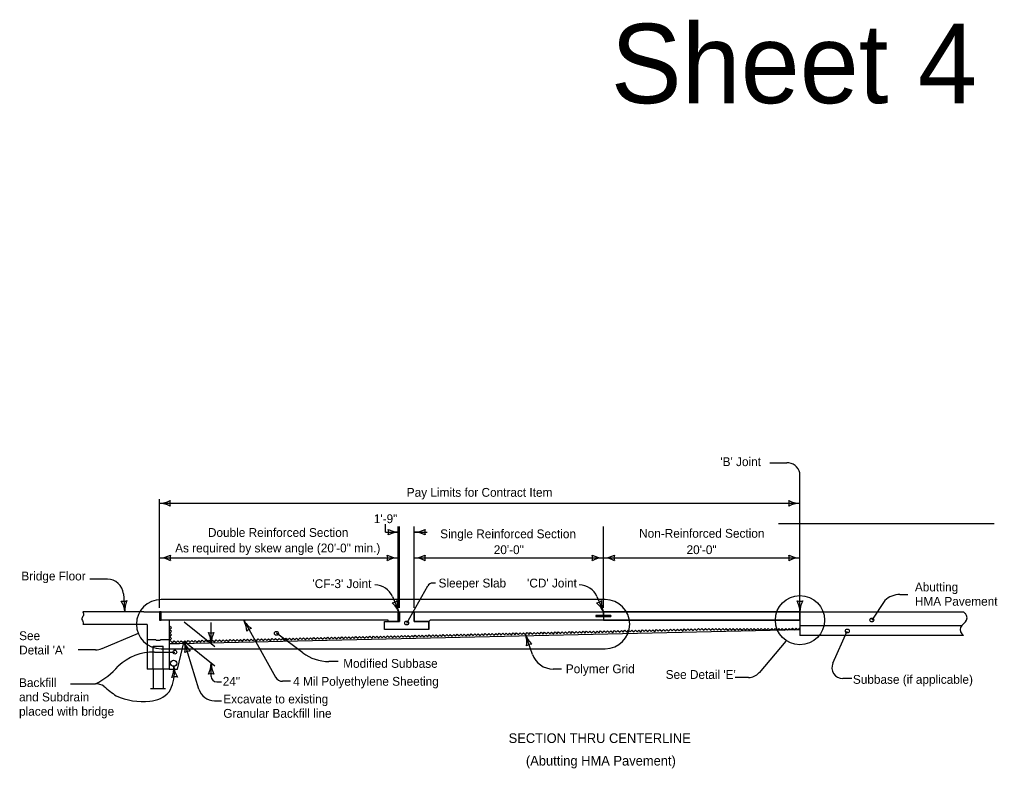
# Model space of a CAD drawing. Extents: x 10028 to 81668, y 6395 to 11634.
# Drawn here: x 21033 to 22806, y 6395 to 7754 of the extents above; entities that cross this region are included whole.
import ezdxf

# ---------------------------------------------------------------- set-up
doc = ezdxf.new("R2010")
doc.units = 0
for name, color, linetype in [('dsnCellElements', 7, 'Continuous'), ('dsnStdBlockNotModified', 7, 'Continuous'), ('dsnStdTextLabel', 7, 'Continuous'), ('dsnStgShadingPropPav', 7, 'Continuous'), ('ShtPlotIdentification', 7, 'Continuous')]:
    doc.layers.add(name, color=color, linetype=linetype)

msp = doc.modelspace()

# ---------------------------------------------------------------- linework, layer by layer
at = {"layer": 'dsnCellElements'}
for p, q in [((21696.4, 6824.1), (21696.4, 6838.8)), ((21696.4, 6824.1), (21721.6, 6824.1)), ((21748.3, 6824.1), (21772.3, 6824.1)), ((21734.9, 6659.2), (21773, 6726.6)), ((21787.2, 6731.7), (21781.7, 6731.7)), ((21289.5, 6664.6), (21289.5, 6679.4)), ((21289.5, 6679.4), (21719.7, 6679.4)), ((21289.5, 6664.6), (21289.5, 6679.4)), ((21719.7, 6679.4), (21719.7, 6675.6)), ((21719.7, 6675.6), (21719.7, 6670.8)), ((21719.7, 6670.8), (21719.7, 6662.2)), ((21721.6, 6672.9), (21721.6, 6671)), ((21748.3, 6676.8), (21748.3, 6679.4)), ((21748.3, 6679.4), (22091.4, 6679.4)), ((21748.3, 6674.5), (21748.3, 6676.8)), ((21748.3, 6672.9), (21748.3, 6674.5)), ((21748.3, 6671), (21748.3, 6672.9)), ((21748.3, 6662.2), (21748.3, 6672.9)), ((22078, 6672.9), (22078, 6671)), ((22091.4, 6672.9), (22078, 6672.9)), ((22078, 6672.9), (22078, 6671)), ((22078, 6671), (22091.4, 6671)), ((22091.4, 6672.9), (22091.4, 6679.4)), ((22091.4, 6679.4), (22091.4, 6672.9)), ((22104.7, 6672.9), (22091.4, 6672.9)), ((22091.4, 6671), (22091.4, 6664.5)), ((21304.7, 6664.6), (21289.5, 6664.6)), ((21326.6, 6664.5), (21304.7, 6664.6)), ((21701.5, 6664.5), (21326.6, 6664.5)), ((21439.5, 6664.5), (21496.8, 6561.2)), ((21701.5, 6662.2), (21701.5, 6664.5)), ((21719.7, 6662.2), (21701.5, 6662.2)), ((21775, 6662.2), (21748.3, 6662.2)), ((21777.5, 6664.5), (21775, 6662.2)), ((22091.4, 6664.5), (21777.5, 6664.5)), ((21277.7, 6606.5), (21314.5, 6606.5)), ((21125.2, 6549.1), (21170.9, 6549.1)), ((21524.1, 6553.5), (21509.9, 6553.5))]:
    msp.add_line(p, q, dxfattribs=at)
for centre, radius, start, end in [((21781.7, 6721.7), 10, 90, 150.5496), ((21275.5, 6515.7), 90.9, 88.6098, 134.2601), ((21107.4, 6674.4), 140.5, 296.876, 318.179), ((21242.5, 6569.5), 71.3, 330.5092, 2.0511), ((21509.9, 6568.5), 15, 209.0167, 270), ((21297.4, 6664.5), 163.6, 227.1442, 236.9942), ((21257.2, 6635.2), 118.5, 245.5915, 275.778), ((21264.5, 6572.1), 55, 274.8506, 316.7198)]:
    msp.add_arc(centre, radius, start, end, dxfattribs=at)
at = {"layer": 'dsnStdBlockNotModified'}
for centre, radius, start, end in [((21685.9, 6824.1), 16.4, 342.2666, 17.7333), ((21721.6, 6866.6), 42.5, 241.9275, 270), ((21748.3, 6866.6), 42.5, 270, 298.0725), ((21783.9, 6824.1), 16.4, 162.2666, 197.7334), ((21721.6, 6781.6), 42.5, 90, 118.0725), ((21748.3, 6781.6), 42.5, 61.9275, 90)]:
    msp.add_arc(centre, radius, start, end, dxfattribs=at)
at = {"layer": 'dsnStgShadingPropPav'}
for centre in [(22578.1, 6664.7), (21734.9, 6659.2), (22533.7, 6644.7), (21498.7, 6640.6), (21314.5, 6606.5)]:
    msp.add_circle(centre, 3.54, dxfattribs=at)
at = {"layer": 'ShtPlotIdentification'}
for p, q in [((22393.4, 6950), (22423.8, 6950)), ((22447.8, 6679.4), (22447.8, 6931.6)), ((21286.5, 6686.8), (21286.5, 6883.8)), ((21286.5, 6876.4), (22447.8, 6876.4)), ((21719.7, 6686.8), (21719.7, 6834.4)), ((21721.6, 6686.8), (21721.6, 6834.4)), ((21748.3, 6686.8), (21748.3, 6834.4)), ((22091.4, 6686.8), (22091.4, 6834.4)), ((22409.2, 6839.9), (22800.1, 6839.9)), ((21286.5, 6777.4), (21719.7, 6777.4)), ((21748.3, 6777.4), (22091.4, 6777.4)), ((22091.4, 6777.4), (22447.8, 6777.4)), ((21192.2, 6739), (21160.5, 6739)), ((21221.3, 6711.9), (21224.1, 6679.4)), ((22094.6, 6701.6), (21289.5, 6701.6)), ((21709.1, 6707.1), (21720.6, 6679.4)), ((22079.8, 6707.1), (22091.4, 6679.4)), ((22628.9, 6710.9), (22643.7, 6710.9)), ((22601.9, 6700.3), (22578.1, 6664.7)), ((21258.3, 6679.4), (21147.6, 6679.4)), ((21258.3, 6679.4), (21286.5, 6679.4)), ((21286.5, 6679.4), (21286.5, 6664.6)), ((21289.5, 6679.4), (21286.5, 6679.4)), ((21286.5, 6676), (21289.5, 6679)), ((21286.5, 6678.1), (21287.3, 6679)), ((21289.5, 6679), (21286.5, 6679)), ((21286.5, 6673.9), (21289.5, 6676.9)), ((21286.5, 6671.8), (21289.5, 6674.8)), ((21286.5, 6669.7), (21289.5, 6672.7)), ((21286.5, 6667.6), (21289.5, 6670.6)), ((21286.5, 6665.5), (21289.5, 6668.5)), ((21287.7, 6664.6), (21289.5, 6666.4)), ((21289.5, 6679.4), (21719.7, 6679.4)), ((21719.7, 6679.4), (21721.6, 6679.4)), ((21719.7, 6662.2), (21719.7, 6679.4)), ((21719.7, 6679.4), (21719.7, 6662.2)), ((21721.6, 6679.4), (21721.6, 6662.2)), ((21721.6, 6679.4), (21748.3, 6679.4)), ((21721.6, 6679.4), (21721.6, 6662.2)), ((21721.6, 6679.4), (21748.3, 6679.4)), ((21721.6, 6662.2), (21721.6, 6679.4)), ((21748.3, 6662.2), (21748.3, 6679.4)), ((21748.3, 6679.4), (22447.8, 6679.4)), ((21748.3, 6679.4), (21748.3, 6662.2)), ((21748.3, 6672.9), (21748.3, 6671)), ((22078, 6672.9), (22104.7, 6672.9)), ((22078, 6671), (22104.7, 6671)), ((22447.8, 6679.4), (22091.4, 6679.4)), ((22091.4, 6679.4), (22091.4, 6672.9)), ((22091.4, 6679.4), (22091.4, 6664.5)), ((22091.4, 6672.9), (22104.7, 6672.9)), ((22104.7, 6671), (22091.4, 6671)), ((22091.4, 6671), (22091.4, 6664.5)), ((22104.7, 6672.9), (22104.7, 6671)), ((22104.7, 6672.9), (22104.7, 6671)), ((22447.8, 6664.5), (22447.8, 6679.4)), ((22447.8, 6679.4), (22744.6, 6679.4)), ((22447.8, 6679.4), (22447.8, 6664.5)), ((22729.9, 6679.4), (22729.9, 6679.4)), ((22747.7, 6676.2), (22744.6, 6679.4)), ((21264.2, 6656.5), (21147.6, 6656.5)), ((21264.2, 6656.5), (21264.2, 6575.6)), ((21286.5, 6664.6), (21289.5, 6664.6)), ((21701.5, 6664.5), (21289.5, 6664.5)), ((21304.3, 6664.6), (21304.3, 6575.6)), ((21331.6, 6661.6), (21386.9, 6616.6)), ((21380.4, 6621.8), (21380.4, 6660)), ((21694.9, 6647.3), (21694.9, 6662.2)), ((21694.9, 6662.2), (21701.5, 6662.2)), ((21694.9, 6647.3), (21694.9, 6662.2)), ((21694.9, 6662.2), (21701.5, 6662.2)), ((21701.5, 6662.2), (21701.5, 6664.5)), ((21701.5, 6662.2), (21721.6, 6662.2)), ((21701.5, 6662.2), (21721.6, 6662.2)), ((21721.6, 6662.2), (21719.7, 6662.2)), ((21775, 6662.2), (21748.3, 6662.2)), ((21748.3, 6662.2), (21775, 6662.2)), ((21775, 6662.2), (21777.5, 6664.5)), ((21775, 6647.3), (21775, 6662.2)), ((21775, 6662.2), (21775, 6647.3)), ((22447.8, 6664.5), (21777.5, 6664.5)), ((22091.4, 6664.5), (22447.8, 6664.5)), ((22447.8, 6664.5), (22447.8, 6636.8)), ((22447.8, 6654.6), (22741.2, 6654.6)), ((22741.4, 6654.9), (22747.7, 6661.1)), ((21248.3, 6640.1), (21182.1, 6612.7)), ((22447.8, 6646.9), (21323.1, 6621.5)), ((21546.7, 6605), (21498.7, 6640.6)), ((21775, 6647.3), (21694.9, 6647.3)), ((21775, 6647.3), (21694.9, 6647.3)), ((21962.9, 6602.4), (21950.4, 6638.4)), ((22744.4, 6636.8), (22447.8, 6636.8)), ((22507.4, 6586.4), (22533.7, 6644.7)), ((22744.6, 6636.6), (22741.4, 6639.7)), ((21264.2, 6629.3), (21279.3, 6629.3)), ((21275, 6575.6), (21275, 6617.3)), ((21275, 6617.3), (21293.5, 6617.3)), ((21281.2, 6627.6), (21279.3, 6629.3)), ((21287.3, 6627.6), (21281.2, 6627.6)), ((21287.3, 6627.6), (21289.2, 6629.3)), ((21289.2, 6629.3), (21304.3, 6629.3)), ((21293.5, 6575.6), (21293.5, 6617.3)), ((21323.1, 6621.5), (21304.3, 6621.5)), ((21319.2, 6575.6), (21331.6, 6626.3)), ((21331.6, 6626.3), (21386.9, 6581.3)), ((21358.1, 6539.4), (21331.6, 6626.3)), ((22422.2, 6626.3), (22373.7, 6569.2)), ((21170.8, 6610.5), (21139.2, 6610.5)), ((21289.5, 6612.5), (22094.6, 6612.5)), ((21380.4, 6562.5), (21380.4, 6586.5)), ((21610.8, 6589.4), (21593.9, 6589.4)), ((21304.3, 6575.6), (21264.2, 6575.6)), ((21275, 6575.6), (21275, 6540.7)), ((21293.5, 6575.6), (21293.5, 6540.7)), ((21304.3, 6575.6), (21319.2, 6575.6)), ((22015.6, 6575.8), (22000.3, 6575.8)), ((22354.6, 6560.5), (22330.4, 6560.5)), ((21390.4, 6552.5), (21399, 6552.5)), ((22541.7, 6558.5), (22525.5, 6558.5)), ((21270.7, 6540.7), (21297.7, 6540.7)), ((21386.5, 6518.4), (21399, 6518.4))]:
    msp.add_line(p, q, dxfattribs=at)
for points in [[(21307.3, 6626.4), (21305.5, 6628.1), (21308.6, 6631.3), (21305.4, 6634.4), (21308.5, 6637.6), (21305.2, 6640.7), (21308.3, 6644), (21305.1, 6647.1), (21308.2, 6650.3), (21304.9, 6653.4), (21305.1, 6653.5)], [(22201.9, 6646), (22203.5, 6644.5), (22206.6, 6647.7), (22209.8, 6644.6), (22212.9, 6647.9), (22216.2, 6644.8), (22219.2, 6648), (22222.5, 6644.9), (22225.6, 6648.2), (22228.8, 6645.1), (22231.9, 6648.3), (22235.2, 6645.2), (22238.2, 6648.5), (22241.5, 6645.4), (22244.6, 6648.6), (22247.8, 6645.5), (22250.9, 6648.8), (22254.2, 6645.7), (22257.3, 6648.9), (22260.5, 6645.8), (22263.6, 6649.1), (22266.8, 6646), (22269.9, 6649.2), (22273.2, 6646.1), (22276.3, 6649.4), (22277.9, 6647.8)], [(22277.9, 6648), (22279.5, 6646.4), (22282.6, 6649.6), (22285.8, 6646.4), (22289, 6649.6), (22292.1, 6646.4), (22295.3, 6649.6), (22298.5, 6646.4), (22301.6, 6649.6), (22304.8, 6646.4), (22308, 6649.6), (22311.1, 6646.4), (22314.3, 6649.6), (22317.5, 6646.4), (22320.6, 6649.6), (22323.8, 6646.4), (22327, 6649.6), (22330.1, 6646.4), (22333.3, 6649.6), (22336.5, 6646.5), (22339.6, 6649.6), (22342.8, 6646.5), (22346, 6649.6), (22349.1, 6646.5), (22352.3, 6649.6), (22353.9, 6648.1)], [(22353.9, 6647.8), (22355.5, 6646.3), (22358.6, 6649.4), (22361.8, 6646.3), (22365, 6649.4), (22368.2, 6646.3), (22371.3, 6649.4), (22374.5, 6646.3), (22377.7, 6649.4), (22380.8, 6646.3), (22384, 6649.5), (22387.2, 6646.3), (22390.3, 6649.5), (22393.5, 6646.3), (22396.7, 6649.5), (22399.8, 6646.3), (22403, 6649.5), (22406.2, 6646.3), (22409.3, 6649.5), (22412.5, 6646.3), (22415.7, 6649.5), (22418.8, 6646.3), (22422, 6649.5), (22425.2, 6646.3), (22428.3, 6649.5), (22429.9, 6647.9)], [(22429.9, 6648.3), (22431.5, 6646.7), (22434.6, 6649.9), (22437.8, 6646.7), (22441, 6649.9), (22444.2, 6646.7), (22447.3, 6649.9), (22447.8, 6649.4)], [(21441.8, 6628.2), (21443.4, 6626.7), (21446.5, 6629.9), (21449.7, 6626.8), (21452.8, 6630.1), (21456, 6627), (21459.1, 6630.2), (21462.4, 6627.1), (21465.5, 6630.4), (21468.7, 6627.3), (21471.8, 6630.5), (21475, 6627.4), (21478.1, 6630.7), (21481.4, 6627.6), (21484.5, 6630.8), (21487.7, 6627.7), (21490.8, 6631), (21494, 6627.9), (21497.1, 6631.1), (21500.4, 6628), (21503.5, 6631.3), (21506.7, 6628.2), (21509.8, 6631.4), (21513.1, 6628.3), (21516.1, 6631.6), (21517.8, 6630)], [(21517.8, 6630), (21519.4, 6628.5), (21522.5, 6631.7), (21525.7, 6628.6), (21528.8, 6631.9), (21532.1, 6628.8), (21535.1, 6632), (21538.4, 6628.9), (21541.5, 6632.2), (21544.7, 6629.1), (21547.8, 6632.3), (21551.1, 6629.2), (21554.2, 6632.5), (21557.4, 6629.4), (21560.5, 6632.6), (21563.7, 6629.5), (21566.8, 6632.8), (21570.1, 6629.7), (21573.2, 6632.9), (21576.4, 6629.8), (21579.5, 6633.1), (21582.7, 6630), (21585.8, 6633.2), (21589.1, 6630.1), (21592.2, 6633.4), (21593.8, 6631.8)], [(21593.8, 6631.8), (21595.4, 6630.3), (21598.5, 6633.5), (21601.7, 6630.4), (21604.8, 6633.7), (21608.1, 6630.6), (21611.2, 6633.8), (21614.4, 6630.7), (21617.5, 6634), (21620.7, 6630.9), (21623.8, 6634.1), (21627.1, 6631), (21630.2, 6634.3), (21633.4, 6631.2), (21636.5, 6634.4), (21639.7, 6631.3), (21642.8, 6634.6), (21646.1, 6631.5), (21649.2, 6634.7), (21652.4, 6631.6), (21655.5, 6634.8), (21658.7, 6631.8), (21661.8, 6635), (21665.1, 6631.9), (21668.2, 6635.1), (21669.8, 6633.6)], [(21669.8, 6633.6), (21671.4, 6632), (21674.5, 6635.3), (21677.7, 6632.2), (21680.8, 6635.4), (21684.1, 6632.3), (21687.2, 6635.6), (21690.4, 6632.5), (21693.5, 6635.7), (21696.7, 6632.6), (21699.8, 6635.9), (21703.1, 6632.8), (21706.2, 6636), (21709.4, 6632.9), (21712.5, 6636.2), (21715.8, 6633.1), (21718.8, 6636.3), (21722.1, 6633.2), (21725.2, 6636.5), (21728.4, 6633.4), (21731.5, 6636.6), (21734.8, 6633.5), (21737.8, 6636.8), (21741.1, 6633.7), (21744.2, 6636.9), (21745.8, 6635.4)], [(21745.8, 6635.4), (21747.4, 6633.8), (21750.5, 6637.1), (21753.8, 6634), (21756.8, 6637.2), (21760.1, 6634.1), (21763.2, 6637.4), (21766.4, 6634.3), (21769.5, 6637.5), (21772.8, 6634.4), (21775.8, 6637.7), (21779.1, 6634.6), (21782.2, 6637.8), (21785.4, 6634.7), (21788.5, 6638), (21791.8, 6634.9), (21794.9, 6638.1), (21798.1, 6635), (21801.2, 6638.3), (21804.4, 6635.2), (21807.5, 6638.4), (21810.8, 6635.3), (21813.9, 6638.6), (21817.1, 6635.5), (21820.2, 6638.7), (21821.8, 6637.2)], [(21821.8, 6637.2), (21823.4, 6635.6), (21826.5, 6638.9), (21829.8, 6635.8), (21832.9, 6639), (21836.1, 6635.9), (21839.2, 6639.2), (21842.4, 6636.1), (21845.5, 6639.3), (21848.8, 6636.2), (21851.9, 6639.5), (21855.1, 6636.4), (21858.2, 6639.6), (21861.4, 6636.5), (21864.5, 6639.8), (21867.8, 6636.7), (21870.9, 6639.9), (21874.1, 6636.8), (21877.2, 6640.1), (21880.4, 6637), (21883.5, 6640.2), (21886.8, 6637.1), (21889.9, 6640.4), (21893.1, 6637.3), (21896.2, 6640.5), (21897.8, 6639)], [(21897.8, 6638.9), (21899.4, 6637.4), (21902.5, 6640.6), (21905.8, 6637.5), (21908.9, 6640.8), (21912.1, 6637.7), (21915.2, 6640.9), (21918.4, 6637.8), (21921.5, 6641.1), (21924.8, 6638), (21927.9, 6641.2), (21931.1, 6638.1), (21934.2, 6641.4), (21937.4, 6638.3), (21940.5, 6641.5), (21943.8, 6638.4), (21946.9, 6641.7), (21950.1, 6638.6), (21953.2, 6641.8), (21956.4, 6638.7), (21959.5, 6642), (21962.8, 6638.9), (21965.9, 6642.1), (21969.1, 6639), (21972.2, 6642.3), (21973.8, 6640.7)], [(21973.8, 6640.7), (21975.5, 6639.2), (21978.5, 6642.4), (21981.8, 6639.3), (21984.9, 6642.5), (21988.1, 6639.4), (21991.2, 6642.7), (21994.5, 6639.6), (21997.5, 6642.8), (22000.8, 6639.7), (22003.9, 6643), (22007.1, 6639.9), (22010.2, 6643.1), (22013.5, 6640), (22016.6, 6643.3), (22019.8, 6640.2), (22022.9, 6643.4), (22026.1, 6640.3), (22029.2, 6643.6), (22032.5, 6640.5), (22035.6, 6643.7), (22038.8, 6640.6), (22041.9, 6643.9), (22045.1, 6640.8), (22048.2, 6644), (22049.8, 6642.5)], [(22049.8, 6642.5), (22051.5, 6640.9), (22054.6, 6644.2), (22057.8, 6641.1), (22060.9, 6644.3), (22064.1, 6641.2), (22067.2, 6644.5), (22070.5, 6641.4), (22073.6, 6644.6), (22076.8, 6641.5), (22079.9, 6644.7), (22083.1, 6641.7), (22086.2, 6644.9), (22089.5, 6641.8), (22092.6, 6645), (22095.8, 6642), (22098.9, 6645.2), (22102.1, 6642.1), (22105.2, 6645.3), (22108.5, 6642.3), (22111.6, 6645.5), (22114.8, 6642.4), (22117.9, 6645.6), (22121.1, 6642.5), (22124.2, 6645.8), (22125.9, 6644.2)], [(22125.9, 6644.3), (22127.5, 6642.7), (22130.6, 6646), (22133.8, 6642.9), (22136.9, 6646.1), (22140.1, 6643), (22143.2, 6646.3), (22146.5, 6643.2), (22149.6, 6646.4), (22152.8, 6643.3), (22155.9, 6646.5), (22159.1, 6643.5), (22162.2, 6646.7), (22165.5, 6643.6), (22168.6, 6646.8), (22171.8, 6643.7), (22174.9, 6647), (22178.2, 6643.9), (22181.2, 6647.1), (22184.5, 6644), (22187.6, 6647.3), (22190.8, 6644.2), (22193.9, 6647.4), (22197.2, 6644.3), (22200.2, 6647.6), (22201.9, 6646)], [(21307, 6626.5), (21307.1, 6626.6), (21310.4, 6623.5), (21313.4, 6626.7), (21316.7, 6623.7), (21319.8, 6626.9), (21323, 6623.8), (21326.1, 6627), (21329.4, 6624), (21332.5, 6627.2), (21335.7, 6624.1), (21338.8, 6627.3), (21342, 6624.2), (21345.1, 6627.5), (21348.4, 6624.4), (21351.5, 6627.6), (21354.7, 6624.5), (21357.8, 6627.8), (21361, 6624.7), (21364.1, 6627.9), (21365.7, 6626.4)], [(21365.7, 6626.5), (21367.4, 6624.9), (21370.5, 6628.2), (21373.7, 6625.1), (21376.8, 6628.3), (21380, 6625.2), (21383.1, 6628.4), (21386.4, 6625.4), (21389.5, 6628.6), (21392.7, 6625.5), (21395.8, 6628.7), (21399, 6625.7), (21402.1, 6628.9), (21405.4, 6625.8), (21408.5, 6629), (21411.7, 6626), (21414.8, 6629.2), (21418, 6626.1), (21421.1, 6629.3), (21424.4, 6626.2), (21427.5, 6629.5), (21430.7, 6626.4), (21433.8, 6629.6), (21437, 6626.5), (21440.1, 6629.8), (21441.8, 6628.2)]]:
    msp.add_lwpolyline(points, dxfattribs=at)
for centre, radius in [((22447.8, 6664.5), 44.6), ((21312.3, 6586.3), 5.57)]:
    msp.add_circle(centre, radius, dxfattribs=at)
for centre, radius, start, end in [((22423.8, 6925.2), 24.8, 15.0299, 90), ((21285.9, 6919.1), 42.7, 270, 298.0725), ((21321.7, 6876.4), 16.5, 162.2666, 197.7334), ((22411.9, 6876.4), 16.5, 342.2666, 17.7333), ((22447.8, 6919.1), 42.7, 241.9275, 270), ((21285.9, 6833.6), 42.7, 61.9275, 90), ((22447.8, 6833.6), 42.7, 90, 118.0725), ((21286.5, 6820.1), 42.7, 270, 298.0725), ((21286.5, 6734.6), 42.7, 61.9275, 90), ((21322.3, 6777.4), 16.5, 162.2666, 197.7334), ((21683.9, 6777.4), 16.5, 342.2666, 17.7333), ((21719.7, 6820.1), 42.7, 241.9275, 270), ((21719.7, 6734.6), 42.7, 90, 118.0725), ((21748.3, 6820.1), 42.7, 270, 298.0725), ((21748.3, 6734.6), 42.7, 61.9275, 90), ((21784.2, 6777.4), 16.5, 162.2666, 197.7334), ((22055.5, 6777.4), 16.5, 342.2666, 17.7333), ((22091.4, 6820.1), 42.7, 241.9275, 270), ((22091.4, 6734.6), 42.7, 90, 118.0725), ((22091.4, 6820.1), 42.7, 270, 298.0725), ((22091.4, 6734.6), 42.7, 61.9275, 90), ((22127.2, 6777.4), 16.5, 162.2666, 197.7334), ((22411.9, 6777.4), 16.5, 342.2666, 17.7333), ((22447.8, 6820.1), 42.7, 241.9275, 270), ((22447.8, 6734.6), 42.7, 90, 118.0725), ((21191.7, 6709.3), 29.7, 4.9696, 89.1065), ((21677.1, 6693.8), 34.7, 22.5907, 90), ((22047.8, 6693.8), 34.7, 22.5907, 90), ((21289.5, 6657.1), 44.6, 90, 269.9998), ((22094.6, 6657.1), 44.6, 270.0002, 90), ((22628.9, 6671.3), 39.6, 90, 132.998), ((21221, 6715.1), 16.5, 257.2356, 292.7023), ((21181.5, 6675.7), 42.7, 4.969, 33.0415), ((21266.7, 6683.1), 42.7, 156.8965, 184.969), ((21706.9, 6712.5), 16.5, 274.8595, 310.3262), ((21681.2, 6662.9), 42.7, 22.5928, 50.6653), ((21760.1, 6695.8), 42.7, 174.5203, 202.5928), ((22077.6, 6712.5), 16.5, 274.8572, 310.3239), ((22051.9, 6662.9), 42.7, 22.5905, 50.663), ((22130.8, 6695.8), 42.7, 174.5181, 202.5905), ((22447.8, 6715.2), 16.5, 252.2666, 287.7333), ((22405, 6679.4), 42.7, 360, 28.0725), ((22490.5, 6679.4), 42.7, 151.9275, 180), ((22740.1, 6668.7), 10.7, 315, 45), ((21476.8, 6685.3), 42.7, 209.0167, 237.0892), ((21402.1, 6643.8), 42.7, 0.9442, 29.0167), ((21456.8, 6633.2), 16.5, 101.2834, 136.7501), ((22749, 6647.3), 10.7, 135, 225), ((21380.4, 6657.7), 16.5, 252.2666, 287.7333), ((21337.7, 6621.8), 42.7, 360, 28.0725), ((21423.1, 6621.8), 42.7, 151.9275, 180), ((21990.8, 6652.4), 42.7, 199.1779, 227.2504), ((21910, 6624.3), 42.7, 351.1054, 19.1779), ((21170.7, 6640.2), 29.7, 270, 292.4496), ((21372.5, 6638.7), 42.7, 196.9537, 225.0262), ((21290.7, 6613.8), 42.7, 348.8812, 16.9537), ((21962.2, 6604.5), 16.5, 91.4446, 126.9113), ((21342, 6592), 16.5, 89.2203, 124.687), ((21593.9, 6668.6), 79.2, 233.4243, 270), ((22000.3, 6615.4), 39.6, 199.1769, 270), ((21270.2, 6576.9), 42.5, 337.1139, 5.1864), ((21354.8, 6584.6), 42.5, 185.1864, 213.2589), ((21337.7, 6586.5), 42.7, 331.9275, 360), ((21423.1, 6586.5), 42.7, 180, 208.0725), ((22525.5, 6578.3), 19.8, 155.762, 270), ((21315.7, 6545.2), 16.4, 77.453, 112.9197), ((21380.4, 6550.7), 16.5, 72.2666, 107.7334), ((21390.4, 6562.5), 10, 180, 270), ((22354.6, 6585.5), 25, 270, 319.6052), ((21170.9, 6521.4), 27.7, 56.8248, 90), ((21386.5, 6548.1), 29.7, 196.9535, 270)]:
    msp.add_arc(centre, radius, start, end, dxfattribs=at)
msp.add_spline([(21147.6, 6679.4), (21148.8, 6673.4), (21145.8, 6667.4), (21148.6, 6659.8), (21148.2, 6656.5)], degree=3, dxfattribs=at)

# ---------------------------------------------------------------- texts
at = {"layer": 'dsnCellElements'}
for s, height, p in [("'B' Joint", 16, (22303.6, 6943.8)), ('Pay Limits for Contract Item', 16, (21735, 6888.2)), ('1\'-9"', 16, (21675.3, 6840.4)), ('Double Reinforced Section', 16, (21374.6, 6815.4)), ('Single Reinforced Section', 16, (21795.6, 6813)), ('Non-Reinforced Section', 16, (22156.3, 6813.9)), ('As required by skew angle (20\'-0" min.)', 16, (21315.1, 6787.3)), ('20\'-0"', 16, (21892.7, 6784.2)), ('20\'-0"', 16, (22242.2, 6784.2)), ('Bridge Floor', 16, (21036.3, 6736.5)), ("'CF-3' Joint", 16, (21564.1, 6722.6)), ('Sleeper Slab', 16, (21792.6, 6723.7)), ("'CD' Joint", 16, (21953.2, 6723.7)), ('Abutting', 16, (22656.2, 6716.6)), ('HMA Pavement', 16, (22656.2, 6690.6)), ('See', 16, (21032.3, 6628.2)), ("Detail 'A'", 16, (21032.3, 6602.2)), ('Modified Subbase', 16, (21619.8, 6578)), ('Polymer Grid', 16, (22023.4, 6568.2)), ('Backfill', 16, (21032.1, 6543.1)), ('24"', 16, (21401.4, 6545.5)), ('4 Mil Polyethylene Sheeting', 16, (21529, 6545.5)), ("See Detail 'E'", 16, (22204.4, 6557.9)), ('Subbase (if applicable)', 16, (22543.8, 6549)), ('and Subdrain', 16, (21032.1, 6517.1)), ('Excavate to existing', 16, (21402.4, 6513.4)), ('placed with bridge', 16, (21032.1, 6491.1)), ('Granular Backfill line', 16, (21402.4, 6487.4)), ('(Abutting HMA Pavement)', 17.5, (21951, 6400.8))]:
    msp.add_text(s, height=height, dxfattribs=at).set_placement(p)
at = {"layer": 'dsnStdTextLabel'}
msp.add_text('Sheet 4', height=144, dxfattribs=at).set_placement((22104.9, 7602))
at = {"layer": 'ShtPlotIdentification'}
msp.add_text('SECTION THRU CENTERLINE', height=17.5, dxfattribs=at).set_placement((21919.7, 6441.7))

doc.saveas('drawing.dxf')
